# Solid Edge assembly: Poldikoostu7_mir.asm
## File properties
Author: Türk
Template: Iso Assembly.asm
Last saved by: Türk
Revision: 2
Application: Solid Edge
Username: Türk
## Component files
Polt220x20.par
Mutter.par
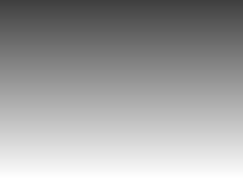
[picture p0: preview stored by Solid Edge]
